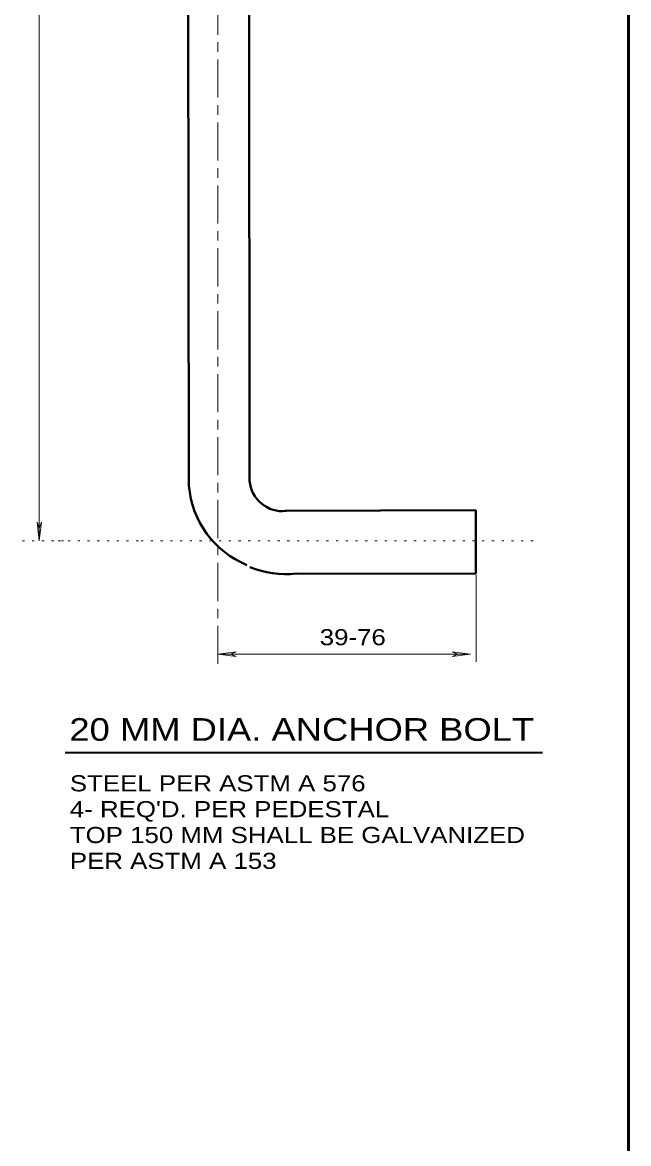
# Model space of a CAD drawing. Extents: x 312583 to 312854, y 144419 to 144597.
# Drawn here: x 312768.1 to 312796.7, y 144488.9 to 144541.9 of the extents above; entities that cross this region are included whole.
import ezdxf
from ezdxf.enums import TextEntityAlignment as Align

# ---------------------------------------------------------------- set-up
doc = ezdxf.new("R2010")
doc.units = 0
doc.header["$LTSCALE"] = 0.3
doc.linetypes.add('DOTTED', pattern=[1.5, 0.3, -1.2])
doc.linetypes.add('LONG_DASH_SHORT_DASH', pattern=[9.9, 6, -1.2, 1.5, -1.2])
doc.layers.add('1', color=7, linetype='Continuous', lineweight=40)
doc.layers.add('2', color=7, linetype='Continuous', lineweight=13)

msp = doc.modelspace()

# ---------------------------------------------------------------- linework, layer by layer
at = {"layer": '1', "lineweight": 53}
msp.add_line((312796.6723, 144460.1131), (312796.6723, 144585.0846), dxfattribs=at)
at = {"layer": '1', "linetype": 'LONG_DASH_SHORT_DASH', "lineweight": 13}
msp.add_line((312777.2876, 144511.5796), (312777.2876, 144582.5116), dxfattribs=at)
at = {"layer": '1'}
for p, q in [((312775.9153, 144519.9976), (312775.8463, 144574.5153)), ((312778.7826, 144520.2276), (312778.7213, 144574.4463)), ((312780.4616, 144518.8016), (312789.4623, 144518.8399)), ((312789.4623, 144515.8576), (312789.4623, 144518.8399)), ((312780.8373, 144515.8346), (312789.4623, 144515.8576))]:
    msp.add_line(p, q, dxfattribs=at)
at = {"layer": '1', "linetype": 'DOTTED', "lineweight": 13}
for p, q in [((312768.057, 144517.3986), (312770.058, 144517.3986)), ((312769.7513, 144517.3986), (312773.6613, 144517.3986)), ((312773.6613, 144517.3986), (312792.3595, 144517.3986))]:
    msp.add_line(p, q, dxfattribs=at)
at = {"layer": '1', "lineweight": 35}
msp.add_line((312770.0796, 144507.4022), (312792.6155, 144507.4022), dxfattribs=at)
at = {"layer": '1'}
for centre, radius, start, end in [((312780.3351, 144520.3464), 4.4314, 184.58752, 247.61561), ((312780.334, 144520.3482), 1.5564, 184.58752, 276.40511), ((312780.4846, 144520.2468), 4.4314, 247.61561, 276.43684)]:
    msp.add_arc(centre, radius, start, end, dxfattribs=at)
at = {"layer": '2'}
for p, q in [((312768.8543, 144517.3986), (312768.8543, 144575.3509)), ((312768.747, 144518.2649), (312768.8543, 144517.9889)), ((312768.8543, 144517.3986), (312768.747, 144518.2649)), ((312768.747, 144518.2649), (312768.8543, 144517.9889)), ((312768.8543, 144517.3986), (312768.747, 144518.2649)), ((312768.9616, 144518.2649), (312768.8543, 144517.9889)), ((312768.8543, 144517.3986), (312768.9616, 144518.2649)), ((312768.9616, 144518.2649), (312768.8543, 144517.9889)), ((312768.8543, 144517.3986), (312768.9616, 144518.2649)), ((312789.4776, 144511.6793), (312789.4776, 144515.7886)), ((312777.2876, 144512.0473), (312778.154, 144512.1546)), ((312777.2876, 144512.0473), (312778.154, 144512.1546)), ((312777.2876, 144512.0473), (312789.2093, 144512.0473)), ((312777.2876, 144512.0473), (312778.154, 144511.9399)), ((312777.2876, 144512.0473), (312778.154, 144511.9399)), ((312778.154, 144512.1546), (312777.878, 144512.0473)), ((312778.154, 144512.1546), (312777.878, 144512.0473)), ((312778.154, 144511.9399), (312777.878, 144512.0473)), ((312778.154, 144511.9399), (312777.878, 144512.0473)), ((312788.343, 144512.1546), (312788.619, 144512.0473)), ((312789.2093, 144512.0473), (312788.343, 144512.1546)), ((312788.343, 144511.9399), (312788.619, 144512.0473)), ((312789.2093, 144512.0473), (312788.343, 144511.9399))]:
    msp.add_line(p, q, dxfattribs=at)

# ---------------------------------------------------------------- texts
at = {"layer": '2', "width": 1.2}
for s, p in [('39-76', (312782.0923, 144512.4641)), ('STEEL PER ASTM A 576', (312770.2956, 144505.5679)), ("4- REQ'D. PER PEDESTAL", (312770.2956, 144504.3479)), ('TOP 150 MM SHALL BE GALVANIZED', (312770.2956, 144503.1279)), ('PER ASTM A 153', (312770.2956, 144501.9079))]:
    msp.add_text(s, height=0.76, dxfattribs=at).set_placement(p)
msp.add_text('20 MM DIA. ANCHOR BOLT', height=1.07, dxfattribs=at).set_placement((312781.244, 144507.9528), align=Align.CENTER)

doc.saveas('drawing.dxf')
